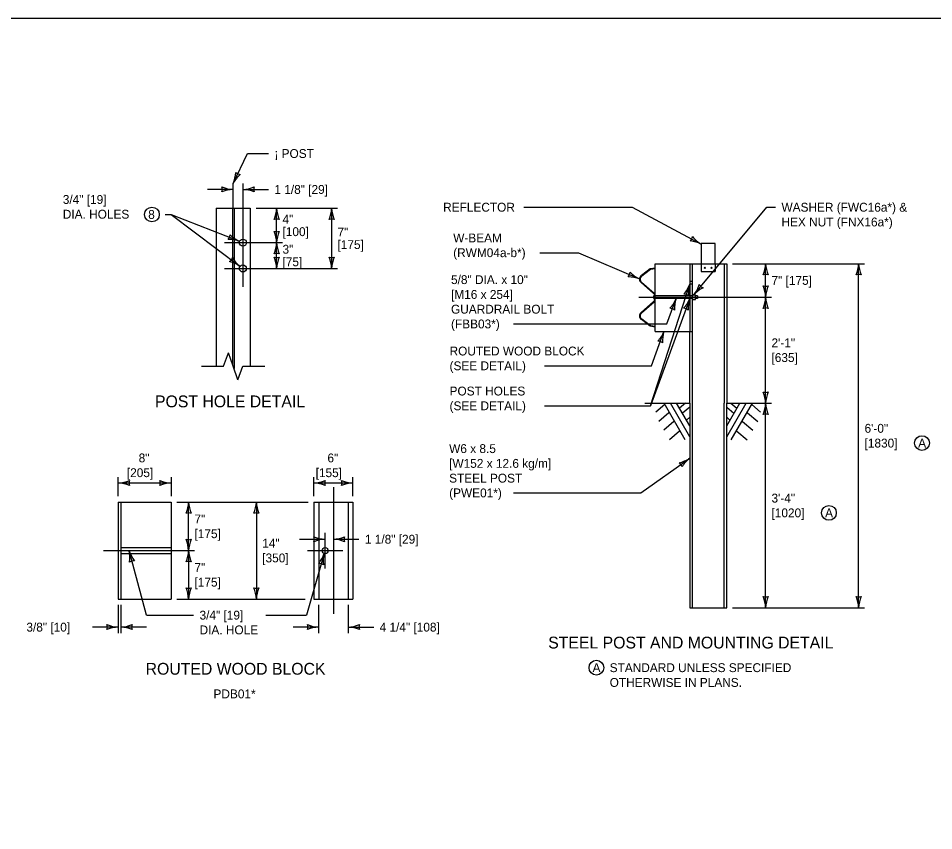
# Model space of a CAD drawing. Extents: x 49991.4 to 50021, y 49987.6 to 50011.4.
# Drawn here: x 50003.26 to 50009.46, y 49993.5 to 49999 of the extents above; entities that cross this region are included whole.
import ezdxf

# ---------------------------------------------------------------- set-up
doc = ezdxf.new("R2010")
doc.units = 0
for name, color, linetype in [('Level 1', 7, 'Continuous'), ('Level 2', 7, 'Continuous'), ('Level 3', 7, 'Continuous'), ('Level 4', 7, 'Continuous'), ('Level 5', 7, 'Continuous'), ('Level 6', 7, 'Continuous')]:
    doc.layers.add(name, color=color, linetype=linetype)

msp = doc.modelspace()

# ---------------------------------------------------------------- linework, layer by layer
at = {"layer": 'Level 1'}
for p, q in [((50004.6024, 49997.7133), (50004.8322, 49997.7133)), ((50004.6024, 49997.7133), (50004.6024, 49996.6424)), ((50004.8322, 49997.7133), (50004.8322, 49996.6424)), ((50007.8879, 49997.4748), (50007.8879, 49997.3373)), ((50007.9816, 49997.4748), (50007.8879, 49997.4748)), ((50007.9816, 49997.3373), (50007.9816, 49997.4748)), ((50007.5756, 49997.3373), (50007.8879, 49997.3373)), ((50007.5756, 49996.8783), (50007.5756, 49997.3373)), ((50007.8257, 49997.3373), (50007.8257, 49996.3924)), ((50007.8879, 49997.3373), (50007.8879, 49997.2848)), ((50007.8879, 49997.3373), (50007.9816, 49997.3373)), ((50007.9816, 49997.3373), (50008.0599, 49997.3373)), ((50007.9816, 49997.3373), (50007.9816, 49997.2848)), ((50008.044, 49997.3373), (50008.044, 49996.3924)), ((50008.0599, 49997.3373), (50008.0599, 49996.3924)), ((50007.5416, 49997.3017), (50007.4819, 49997.257)), ((50007.5432, 49997.2981), (50007.4842, 49997.2539)), ((50007.5756, 49997.3078), (50007.5416, 49997.3017)), ((50007.5756, 49997.3036), (50007.5432, 49997.2981)), ((50007.8879, 49997.2848), (50007.9816, 49997.2848)), ((50007.4801, 49997.2092), (50007.5652, 49997.135)), ((50007.4827, 49997.2121), (50007.5678, 49997.138)), ((50007.4801, 49997.0068), (50007.565, 49997.0807)), ((50007.4827, 49997.0038), (50007.5691, 49997.0792)), ((50007.5737, 49997.1108), (50007.5639, 49997.1108)), ((50007.8257, 49997.1312), (50007.8276, 49997.1312)), ((50007.8257, 49997.0901), (50007.8276, 49997.0901)), ((50007.8276, 49997.1312), (50007.8276, 49997.0901)), ((50007.8276, 49997.1108), (50007.8492, 49997.1108)), ((50007.8277, 49997.1273), (50007.8492, 49997.1273)), ((50007.8277, 49997.0943), (50007.8492, 49997.0943)), ((50007.8492, 49997.0943), (50007.8492, 49997.1273)), ((50007.8623, 49997.1204), (50007.8492, 49997.1204)), ((50007.8623, 49997.101), (50007.8492, 49997.101)), ((50007.8623, 49997.1204), (50007.8623, 49997.101)), ((50007.5416, 49996.9138), (50007.4819, 49996.959)), ((50007.5432, 49996.9175), (50007.4842, 49996.9621)), ((50007.5756, 49996.9078), (50007.5416, 49996.9138)), ((50007.5756, 49996.9118), (50007.5432, 49996.9175)), ((50007.5756, 49996.8783), (50007.8257, 49996.8783)), ((50007.8098, 49996.3924), (50007.8098, 49996.8783)), ((50007.5052, 49996.3924), (50007.8098, 49996.3924)), ((50007.64, 49996.3829), (50007.5795, 49996.3321)), ((50007.7785, 49996.1448), (50007.6358, 49996.3924)), ((50007.8098, 49996.165), (50007.6785, 49996.3924)), ((50007.8098, 49996.2387), (50007.7211, 49996.3924)), ((50007.781, 49996.3924), (50007.7407, 49996.3585)), ((50007.8098, 49996.3654), (50007.7615, 49996.3248)), ((50008.0599, 49996.3924), (50008.3636, 49996.3924)), ((50008.0599, 49996.165), (50008.1911, 49996.3924)), ((50008.0599, 49996.2387), (50008.1484, 49996.3924)), ((50008.0599, 49996.3654), (50008.1081, 49996.3248)), ((50008.0887, 49996.3924), (50008.129, 49996.3585)), ((50008.0912, 49996.1448), (50008.2339, 49996.3924)), ((50008.2297, 49996.3829), (50008.2901, 49996.3321)), ((50007.6679, 49996.327), (50007.5993, 49996.2694)), ((50007.8098, 49996.2972), (50007.7872, 49996.2781)), ((50008.0599, 49996.2972), (50008.0824, 49996.2781)), ((50008.2017, 49996.327), (50008.2703, 49996.2694)), ((50007.703, 49996.2688), (50007.6336, 49996.2106)), ((50008.1667, 49996.2688), (50008.236, 49996.2106)), ((50007.7414, 49996.2035), (50007.672, 49996.1453)), ((50008.1283, 49996.2035), (50008.1976, 49996.1453)), ((50003.9385, 49995.7231), (50004.2961, 49995.7231)), ((50003.9385, 49995.7231), (50003.9385, 49995.0664)), ((50004.2961, 49995.7231), (50004.2961, 49995.0664)), ((50005.2641, 49995.7231), (50005.2641, 49995.0664)), ((50005.2641, 49995.7231), (50005.5279, 49995.7231)), ((50005.2963, 49995.7231), (50005.2963, 49995.0664)), ((50005.4957, 49995.7231), (50005.4957, 49995.0664)), ((50005.5279, 49995.7231), (50005.5279, 49995.0664)), ((50003.9385, 49995.0664), (50004.2961, 49995.0664)), ((50005.2641, 49995.0664), (50005.5279, 49995.0664))]:
    msp.add_line(p, q, dxfattribs=at)
msp.add_lwpolyline([(49999.3835, 49998.9992), (50016.7501, 49998.9992), (50016.7501, 49987.7988), (49999.3835, 49987.7988)], close=True, dxfattribs=at)
for centre, radius in [((50004.7829, 49997.4803), 0.0237), ((50004.7829, 49997.305), 0.0237), ((50007.9121, 49997.309), 0.004), ((50007.9573, 49997.309), 0.004), ((50005.3403, 49995.3947), 0.0205)]:
    msp.add_circle(centre, radius, dxfattribs=at)
for centre, radius, start, end in [((50007.5003, 49997.2324), 0.0308, 126.89692, 228.93931), ((50007.5003, 49997.2324), 0.0269, 126.89692, 228.93931), ((50007.5451, 49997.104), 0.0306, 310.4718, 354.09773), ((50007.5451, 49997.112), 0.0306, 5.90227, 48.93931), ((50007.5451, 49997.112), 0.0345, 28.10432, 48.93931), ((50007.5451, 49997.104), 0.0345, 314.1015, 331.89568), ((50007.5003, 49996.9836), 0.0308, 131.06069, 233.10308), ((50007.5003, 49996.9836), 0.0269, 131.06069, 233.10308)]:
    msp.add_arc(centre, radius, start, end, dxfattribs=at)
for centre, major_axis, ratio, start_param, end_param in [((50007.5736, 49997.1106), (0, 0.0146), 0.663267, 0.091019, 3.253139), ((50007.8407, 49997.1191), (0.00829, 0.00104), 0.990733, 4.587776, 7.59993), ((50007.8406, 49997.1026), (-0.00829, -0.00104), 0.990733, 1.547621, 4.582997)]:
    msp.add_ellipse(centre, major_axis=major_axis, ratio=ratio, start_param=start_param, end_param=end_param, dxfattribs=at)
at = {"layer": 'Level 2'}
for centre in [(50004.1666, 49997.6706), (50009.3828, 49996.1225), (50008.7525, 49995.65), (50007.1774, 49994.6016)]:
    msp.add_circle(centre, 0.05, dxfattribs=at)
at = {"layer": 'Level 3'}
for p, q in [((50004.7173, 49997.8803), (50004.8151, 49998.0835)), ((50004.8151, 49998.0835), (50004.9564, 49998.0835)), ((50004.7173, 49997.8403), (50004.5439, 49997.8403)), ((50004.7829, 49997.8403), (50004.9564, 49997.8403)), ((50004.8722, 49997.7133), (50005.4238, 49997.7133)), ((50005.0114, 49997.4803), (50005.0114, 49997.7133)), ((50005.3839, 49997.7133), (50005.3839, 49997.305)), ((50006.6851, 49997.7199), (50007.4192, 49997.7199)), ((50007.4192, 49997.7199), (50007.8879, 49997.4701)), ((50007.8384, 49997.1273), (50008.3315, 49997.7198)), ((50008.3315, 49997.7198), (50008.3911, 49997.7198)), ((50004.2566, 49997.6706), (50004.2966, 49997.6706)), ((50004.2966, 49997.6706), (50004.764, 49997.3192)), ((50004.2966, 49997.6706), (50004.7609, 49997.489)), ((50005.0114, 49997.305), (50005.0114, 49997.4803)), ((50006.7953, 49997.4118), (50007.0573, 49997.4118)), ((50007.0573, 49997.4118), (50007.4696, 49997.2339)), ((50008.0999, 49997.3373), (50008.9939, 49997.3373)), ((50008.3236, 49997.1108), (50008.3236, 49997.3373)), ((50008.9539, 49995.0076), (50008.9539, 49997.3373)), ((50007.5435, 49996.375), (50007.8098, 49997.1982)), ((50007.8098, 49997.101), (50007.5435, 49996.375)), ((50007.654, 49996.9294), (50007.717, 49997.101)), ((50008.3236, 49996.3924), (50008.3236, 49997.1108)), ((50006.6167, 49996.9294), (50007.654, 49996.9294)), ((50007.55, 49996.646), (50007.6352, 49996.8783)), ((50006.8267, 49996.646), (50007.55, 49996.646)), ((50006.8267, 49996.375), (50007.5435, 49996.375)), ((50008.3236, 49995.0076), (50008.3236, 49996.3924)), ((50007.4788, 49995.7851), (50007.8098, 49996.0196)), ((50003.9385, 49995.7631), (50003.9385, 49995.892)), ((50004.2961, 49995.852), (50003.9385, 49995.852)), ((50004.2961, 49995.892), (50004.2961, 49995.7631)), ((50005.2641, 49995.7631), (50005.2641, 49995.892)), ((50005.5279, 49995.852), (50005.2641, 49995.852)), ((50005.5279, 49995.7631), (50005.5279, 49995.892)), ((50006.6167, 49995.7851), (50007.4788, 49995.7851)), ((50004.3361, 49995.7231), (50005.2241, 49995.7231)), ((50004.4151, 49995.3947), (50004.4151, 49995.7231)), ((50004.8741, 49995.7231), (50004.8741, 49995.0664)), ((50005.1669, 49995.4715), (50005.3403, 49995.4715)), ((50005.396, 49995.4715), (50005.5694, 49995.4715)), ((50004.1296, 49994.9573), (50004.0124, 49995.3947)), ((50004.4151, 49995.3947), (50004.4151, 49995.0664)), ((50005.3331, 49995.3755), (50005.2128, 49994.9573)), ((50004.3361, 49995.0664), (50005.2042, 49995.0664)), ((50003.9385, 49995.0264), (50003.9385, 49994.8361)), ((50003.9561, 49995.0264), (50003.9561, 49994.8361)), ((50005.2963, 49994.8361), (50005.2963, 49995.0264)), ((50005.4957, 49995.0264), (50005.4957, 49994.8361)), ((50008.0999, 49995.0076), (50008.9939, 49995.0076)), ((50004.1296, 49994.9573), (50004.4494, 49994.9573)), ((50004.938, 49994.9573), (50005.2128, 49994.9573)), ((50003.9385, 49994.8761), (50003.7651, 49994.8761)), ((50004.1295, 49994.8761), (50003.9561, 49994.8761)), ((50005.2963, 49994.8761), (50005.1229, 49994.8761)), ((50005.4957, 49994.8761), (50005.6691, 49994.8761))]:
    msp.add_line(p, q, dxfattribs=at)
for centre, radius, start, end in [((50004.5026, 49997.9708), 0.233, 337.12584, 356.37569), ((50004.7729, 49997.9958), 0.0548, 226.43734, 262.15971), ((50004.9135, 49997.7757), 0.2223, 131.75454, 151.93804), ((50004.7265, 49998.0624), 0.2223, 247.45601, 267.63952), ((50004.5891, 49997.8403), 0.0548, 342.13882, 17.86118), ((50004.7288, 49997.6076), 0.233, 92.82731, 112.07716), ((50004.7714, 49998.073), 0.233, 272.82731, 292.07716), ((50004.7738, 49997.6181), 0.2223, 67.45601, 87.63952), ((50004.9111, 49997.8403), 0.0548, 162.13882, 197.86118), ((50004.7893, 49997.7225), 0.2223, 337.45601, 357.63952), ((50005.2441, 49997.7248), 0.233, 182.82731, 202.07716), ((50005.1617, 49997.7225), 0.2223, 337.45601, 357.63952), ((50005.6166, 49997.7248), 0.233, 182.82731, 202.07716), ((50005.0114, 49997.5851), 0.0548, 72.13882, 107.86118), ((50005.3839, 49997.5851), 0.0548, 72.13882, 107.86118), ((50004.6415, 49997.5357), 0.0548, 320.76761, 356.48997), ((50004.8503, 49997.6925), 0.2223, 226.0848, 246.26831), ((50005.0114, 49997.6085), 0.0548, 252.13882, 287.86118), ((50004.7787, 49997.4688), 0.233, 2.82731, 22.07716), ((50005.2336, 49997.4712), 0.2223, 157.45601, 177.63952), ((50007.7747, 49997.5304), 0.0548, 314.08214, 349.8045), ((50008.0004, 49997.6618), 0.2223, 219.39933, 239.58284), ((50004.6868, 49997.2681), 0.233, 71.4561, 90.70595), ((50004.7893, 49997.4895), 0.2223, 337.45601, 357.63952), ((50005.2441, 49997.4918), 0.233, 182.82731, 202.07716), ((50007.7885, 49997.2594), 0.233, 64.77063, 84.02048), ((50005.0114, 49997.3521), 0.0548, 72.13882, 107.86118), ((50004.6615, 49997.3963), 0.0548, 305.20124, 340.9236), ((50004.6333, 49997.1263), 0.233, 55.88973, 75.13958), ((50004.9048, 49997.4913), 0.2223, 210.51843, 230.70194), ((50005.0114, 49997.4332), 0.0548, 252.13882, 287.86118), ((50004.7787, 49997.2935), 0.233, 2.82731, 22.07716), ((50005.2336, 49997.2958), 0.2223, 157.45601, 177.63952), ((50005.3839, 49997.4332), 0.0548, 252.13882, 287.86118), ((50005.1512, 49997.2935), 0.233, 2.82731, 22.07716), ((50005.606, 49997.2958), 0.2223, 157.45601, 177.63952), ((50008.1014, 49997.3465), 0.2223, 337.45601, 357.63952), ((50008.5563, 49997.3488), 0.233, 182.82731, 202.07716), ((50008.7317, 49997.3465), 0.2223, 337.45601, 357.63952), ((50009.1866, 49997.3488), 0.233, 182.82731, 202.07716), ((50007.3519, 49997.2847), 0.0548, 318.7908, 354.51316), ((50007.566, 49997.4342), 0.2223, 224.10799, 244.2915), ((50007.3879, 49997.0156), 0.233, 69.47929, 88.72914), ((50008.3236, 49997.2091), 0.0548, 72.13882, 107.86118), ((50008.9539, 49997.2091), 0.0548, 72.13882, 107.86118), ((50007.6012, 49997.2753), 0.2223, 319.53322, 339.71672), ((50008.0347, 49997.1375), 0.233, 164.90452, 184.15437), ((50007.6522, 49997.2673), 0.233, 323.06204, 342.31189), ((50008.0033, 49996.9782), 0.2223, 117.69074, 137.87425), ((50007.9204, 49997.2259), 0.0548, 212.37355, 248.09591), ((50008.3236, 49997.239), 0.0548, 252.13882, 287.86118), ((50008.0909, 49997.0993), 0.233, 2.82731, 22.07716), ((50008.5457, 49997.1017), 0.2223, 157.45601, 177.63952), ((50007.5116, 49997.186), 0.2223, 317.34855, 337.53206), ((50007.9395, 49997.0318), 0.233, 162.71985, 181.9697), ((50007.6044, 49997.1861), 0.2223, 317.31578, 337.49928), ((50007.7703, 49997.0762), 0.0548, 54.21602, 89.93839), ((50008.0322, 49997.0317), 0.233, 162.68708, 181.93693), ((50008.1014, 49997.12), 0.2223, 337.45601, 357.63952), ((50008.5563, 49997.1223), 0.233, 182.82731, 202.07716), ((50007.6729, 49996.9806), 0.0548, 52.03136, 87.75372), ((50007.7656, 49996.9806), 0.0548, 51.99858, 87.72094), ((50008.3236, 49996.9826), 0.0548, 72.13882, 107.86118), ((50007.4298, 49996.9634), 0.2223, 317.32342, 337.50693), ((50007.8576, 49996.809), 0.233, 162.69472, 181.94457), ((50007.5911, 49996.7579), 0.0548, 52.00623, 87.72859), ((50008.3236, 49996.5206), 0.0548, 252.13882, 287.86118), ((50008.0909, 49996.3809), 0.233, 2.82731, 22.07716), ((50008.5457, 49996.3833), 0.2223, 157.45601, 177.63952), ((50008.1014, 49996.4016), 0.2223, 337.45601, 357.63952), ((50008.5563, 49996.4039), 0.233, 182.82731, 202.07716), ((50008.3236, 49996.2642), 0.0548, 72.13882, 107.86118), ((50007.6888, 49996.2061), 0.2223, 282.76822, 302.95173), ((50007.7051, 49995.9455), 0.0548, 17.45103, 53.17339), ((50007.9537, 49995.8363), 0.233, 128.13952, 147.38937), ((50003.927, 49996.0847), 0.233, 272.82731, 292.07716), ((50003.9293, 49995.6299), 0.2223, 67.45601, 87.63952), ((50004.0667, 49995.852), 0.0548, 162.13882, 197.86118), ((50004.3053, 49996.0741), 0.2223, 247.45601, 267.63952), ((50004.1679, 49995.852), 0.0548, 342.13882, 17.86118), ((50004.3076, 49995.6193), 0.233, 92.82731, 112.07716), ((50005.2526, 49996.0847), 0.233, 272.82731, 292.07716), ((50005.2549, 49995.6299), 0.2223, 67.45601, 87.63952), ((50005.3923, 49995.852), 0.0548, 162.13882, 197.86118), ((50005.5371, 49996.0741), 0.2223, 247.45601, 267.63952), ((50005.3997, 49995.852), 0.0548, 342.13882, 17.86118), ((50005.5394, 49995.6193), 0.233, 92.82731, 112.07716), ((50004.193, 49995.7322), 0.2223, 337.45601, 357.63952), ((50004.6479, 49995.7345), 0.233, 182.82731, 202.07716), ((50004.652, 49995.7322), 0.2223, 337.45601, 357.63952), ((50005.1068, 49995.7345), 0.233, 182.82731, 202.07716), ((50004.4151, 49995.5948), 0.0548, 72.13882, 107.86118), ((50004.8741, 49995.5948), 0.0548, 72.13882, 107.86118), ((50004.4151, 49995.523), 0.0548, 252.13882, 287.86118), ((50004.1824, 49995.3833), 0.233, 2.82731, 22.07716), ((50004.6373, 49995.3856), 0.2223, 157.45601, 177.63952), ((50005.3495, 49995.6937), 0.2223, 247.45601, 267.63952), ((50005.2121, 49995.4715), 0.0548, 342.13882, 17.86118), ((50005.3518, 49995.2388), 0.233, 92.82731, 112.07716), ((50005.3845, 49995.7043), 0.233, 272.82731, 292.07716), ((50005.3869, 49995.2494), 0.2223, 67.45601, 87.63952), ((50005.5242, 49995.4715), 0.0548, 162.13882, 197.86118), ((50003.7955, 49995.3461), 0.2223, 352.45601, 12.63952), ((50004.2342, 49995.4661), 0.233, 197.82731, 217.07716), ((50004.193, 49995.4039), 0.2223, 337.45601, 357.63952), ((50004.6479, 49995.4062), 0.233, 182.82731, 202.07716), ((50005.1222, 49995.4457), 0.2223, 321.4053, 341.58881), ((50005.56, 49995.3222), 0.233, 166.7766, 186.02645), ((50004.0456, 49995.2709), 0.0548, 87.13882, 122.86118), ((50004.4151, 49995.2665), 0.0548, 72.13882, 107.86118), ((50005.2977, 49995.2523), 0.0548, 56.08811, 91.81047), ((50004.4151, 49995.1947), 0.0548, 252.13882, 287.86118), ((50004.1824, 49995.0549), 0.233, 2.82731, 22.07716), ((50004.6373, 49995.0573), 0.2223, 157.45601, 177.63952), ((50004.8741, 49995.1947), 0.0548, 252.13882, 287.86118), ((50004.6414, 49995.0549), 0.233, 2.82731, 22.07716), ((50005.0962, 49995.0573), 0.2223, 157.45601, 177.63952), ((50008.3236, 49995.1358), 0.0548, 252.13882, 287.86118), ((50008.0909, 49994.9961), 0.233, 2.82731, 22.07716), ((50008.5457, 49994.9985), 0.2223, 157.45601, 177.63952), ((50008.9539, 49995.1358), 0.0548, 252.13882, 287.86118), ((50008.7212, 49994.9961), 0.233, 2.82731, 22.07716), ((50009.176, 49994.9985), 0.2223, 157.45601, 177.63952), ((50003.9476, 49995.0983), 0.2223, 247.45601, 267.63952), ((50003.8103, 49994.8761), 0.0548, 342.13882, 17.86118), ((50003.95, 49994.6434), 0.233, 92.82731, 112.07716), ((50003.9446, 49995.1089), 0.233, 272.82731, 292.07716), ((50003.9469, 49994.654), 0.2223, 67.45601, 87.63952), ((50004.0843, 49994.8761), 0.0548, 162.13882, 197.86118), ((50005.3055, 49995.0983), 0.2223, 247.45601, 267.63952), ((50005.1681, 49994.8761), 0.0548, 342.13882, 17.86118), ((50005.3078, 49994.6434), 0.233, 92.82731, 112.07716), ((50005.4842, 49995.1089), 0.233, 272.82731, 292.07716), ((50005.4865, 49994.654), 0.2223, 67.45601, 87.63952), ((50005.6239, 49994.8761), 0.0548, 162.13882, 197.86118)]:
    msp.add_arc(centre, radius, start, end, dxfattribs=at)
at = {"layer": 'Level 4'}
for p, q in [((50004.7118, 49997.7133), (50004.7118, 49996.6577)), ((50004.7228, 49997.7133), (50004.7228, 49996.6269)), ((50007.8098, 49997.3373), (50007.8098, 49996.8783)), ((50007.8257, 49997.2176), (50007.8098, 49997.2176)), ((50007.8257, 49997.1982), (50007.8098, 49997.1982)), ((50007.8257, 49997.1204), (50007.5756, 49997.1204)), ((50007.8257, 49997.101), (50007.5756, 49997.101)), ((50007.8098, 49996.3924), (50007.8098, 49995.0076)), ((50007.8257, 49996.3924), (50007.8257, 49995.0076)), ((50008.044, 49995.0076), (50008.044, 49996.3924)), ((50008.0599, 49995.0076), (50008.0599, 49996.3924)), ((50003.9561, 49995.7231), (50003.9561, 49995.0664)), ((50003.9561, 49995.4153), (50004.2961, 49995.4153)), ((50003.9561, 49995.3742), (50004.2961, 49995.3742)), ((50007.8098, 49995.0076), (50008.0599, 49995.0076))]:
    msp.add_line(p, q, dxfattribs=at)
at = {"layer": 'Level 5'}
for p, q in [((50004.7173, 49997.7133), (50004.7173, 49997.8803)), ((50004.7829, 49997.8803), (50004.7829, 49997.1813)), ((50004.6592, 49997.4803), (50005.0514, 49997.4803)), ((50004.6592, 49997.305), (50005.4238, 49997.305)), ((50007.4639, 49997.1108), (50008.3636, 49997.1108)), ((50005.396, 49995.8231), (50005.396, 49994.9664)), ((50005.3403, 49995.2742), (50005.3403, 49995.5152)), ((50003.8385, 49995.3947), (50004.4552, 49995.3947)), ((50005.2198, 49995.3947), (50005.4608, 49995.3947))]:
    msp.add_line(p, q, dxfattribs=at)
at = {"layer": 'Level 6'}
for p, q in [((50004.6525, 49996.6424), (50004.6849, 49996.7338)), ((50004.7173, 49996.6424), (50004.6849, 49996.7338)), ((50004.5024, 49996.6424), (50004.6525, 49996.6424)), ((50004.7497, 49996.551), (50004.7173, 49996.6424)), ((50004.7497, 49996.551), (50004.7821, 49996.6424)), ((50004.7821, 49996.6424), (50004.9322, 49996.6424))]:
    msp.add_line(p, q, dxfattribs=at)

# ---------------------------------------------------------------- texts
at = {"layer": 'Level 2'}
for s, height, p in [('¡ POST', 0.06, (50004.9964, 49998.0535)), ('1 1/8" [29]', 0.06, (50004.9964, 49997.8103)), ('3/4" [19]', 0.06, (50003.5632, 49997.7425)), ('DIA. HOLES', 0.06, (50003.5632, 49997.6425)), ('REFLECTOR', 0.06, (50006.1394, 49997.6899)), ('WASHER (FWC16a*) &', 0.06, (50008.4311, 49997.6898)), ('4"', 0.06, (50005.0514, 49997.6093)), ('HEX NUT (FNX16a*)', 0.06, (50008.4311, 49997.5898)), ('[100]', 0.06, (50005.0514, 49997.5243)), ('7"', 0.06, (50005.4239, 49997.5217)), ('W-BEAM', 0.06, (50006.2076, 49997.4818)), ('3"', 0.06, (50005.0514, 49997.4052)), ('[175]', 0.06, (50005.4239, 49997.4367)), ('(RWM04a-b*)', 0.06, (50006.2076, 49997.3818)), ('[75]', 0.06, (50005.0514, 49997.3202)), ('5/8" DIA. x 10"', 0.06, (50006.1927, 49997.1994)), ('7" [175]', 0.06, (50008.3636, 49997.1941)), ('[M16 x 254]', 0.06, (50006.1927, 49997.0994)), ('GUARDRAIL BOLT', 0.06, (50006.1927, 49996.9994)), ('(FBB03*)', 0.06, (50006.1927, 49996.8994)), ('2\'-1"', 0.06, (50008.3636, 49996.7716)), ('ROUTED WOOD BLOCK', 0.06, (50006.1829, 49996.716)), ('[635]', 0.06, (50008.3636, 49996.6716)), ('(SEE DETAIL)', 0.06, (50006.1829, 49996.616)), ('POST HOLES', 0.06, (50006.1829, 49996.445)), ('POST HOLE DETAIL', 0.08, (50004.1877, 49996.365)), ('(SEE DETAIL)', 0.06, (50006.1829, 49996.345)), ('6\'-0"', 0.06, (50008.9939, 49996.1925)), ('[1830]', 0.06, (50008.9939, 49996.0925)), ('A', 0.06, (50009.357, 49996.0925)), ('W6 x 8.5', 0.06, (50006.1801, 49996.0551)), ('8"', 0.06, (50004.0769, 49995.992)), ('6"', 0.06, (50005.3557, 49995.992)), ('[W152 x 12.6 kg/m]', 0.06, (50006.1801, 49995.9551)), ('[205]', 0.06, (50003.9971, 49995.892)), ('[155]', 0.06, (50005.2758, 49995.892)), ('STEEL POST', 0.06, (50006.1801, 49995.8551)), ('(PWE01*)', 0.06, (50006.1801, 49995.7551)), ('3\'-4"', 0.06, (50008.3636, 49995.72)), ('[1020]', 0.06, (50008.3636, 49995.62)), ('A', 0.06, (50008.7267, 49995.62)), ('7"', 0.06, (50004.4551, 49995.5789)), ('[175]', 0.06, (50004.4551, 49995.4789)), ('14"', 0.06, (50004.9141, 49995.4147)), ('1 1/8" [29]', 0.06, (50005.6094, 49995.4415)), ('[350]', 0.06, (50004.9141, 49995.3147)), ('7"', 0.06, (50004.4551, 49995.2506)), ('[175]', 0.06, (50004.4551, 49995.1506)), ('3/4" [19]', 0.06, (50004.4894, 49994.9273)), ('3/8" [10]', 0.06, (50003.3165, 49994.8461)), ('4 1/4" [108]', 0.06, (50005.7091, 49994.8461)), ('DIA. HOLE', 0.06, (50004.4894, 49994.8273)), ('STEEL POST AND MOUNTING DETAIL', 0.08, (50006.851, 49994.7316)), ('ROUTED WOOD BLOCK', 0.08, (50004.1241, 49994.5541)), ('A', 0.06, (50007.1516, 49994.5716)), ('STANDARD UNLESS SPECIFIED', 0.06, (50007.2674, 49994.5716)), ('OTHERWISE IN PLANS.', 0.06, (50007.2674, 49994.4716)), ('PDB01*', 0.06, (50004.5839, 49994.3941))]:
    msp.add_text(s, height=height, dxfattribs=at).set_placement(p)
at = {"layer": 'Level 4'}
msp.add_text('8', height=0.06, dxfattribs=at).set_placement((50004.1416, 49997.6406))

doc.saveas('drawing.dxf')
